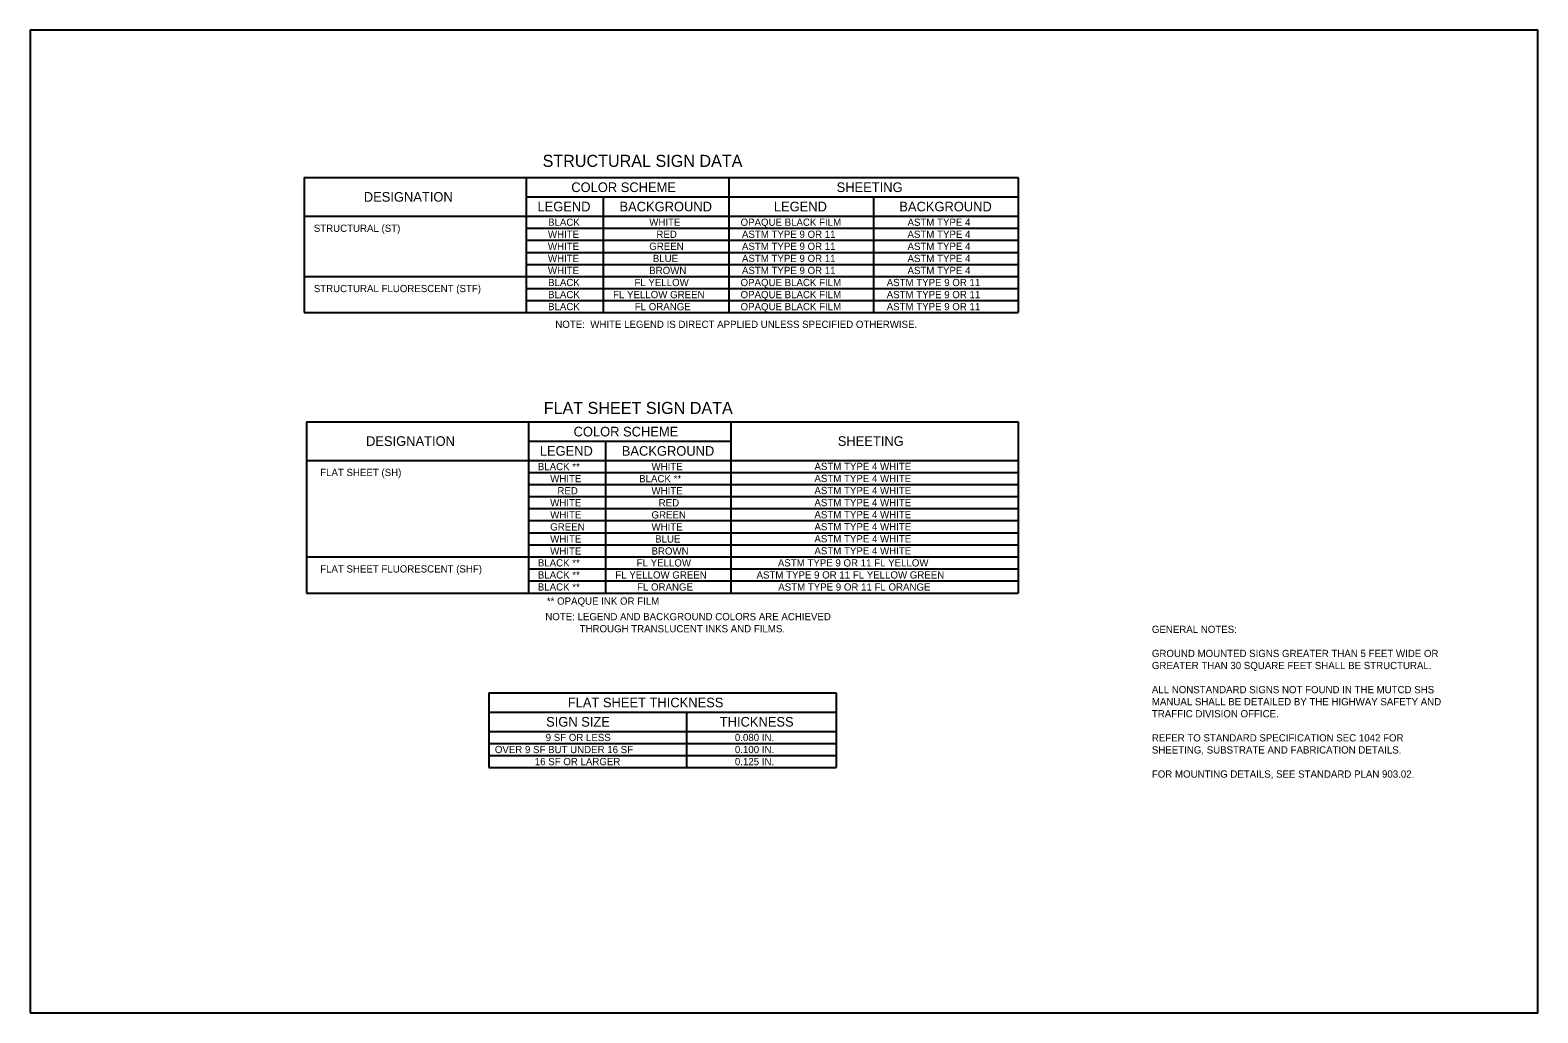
# Model space of a CAD drawing. Extents: x -439.1 to -407.9, y -458.1 to -437.7.
import ezdxf

# ---------------------------------------------------------------- set-up
doc = ezdxf.new("R2010")
doc.units = 0
for name, color, linetype in [('Draft_Named_Boundary', 7, 'Continuous'), ('Level 4', 7, 'Continuous'), ('Level 45', 7, 'Continuous')]:
    doc.layers.add(name, color=color, linetype=linetype)

msp = doc.modelspace()

# ---------------------------------------------------------------- linework, layer by layer
at = {"layer": 'Draft_Named_Boundary'}
msp.add_lwpolyline([(-439.109, -458.051), (-407.859, -458.051), (-407.859, -437.676), (-439.109, -437.676)], close=True, dxfattribs=at)
at = {"layer": 'Level 4'}
for p, q in [((-433.43, -440.733), (-433.43, -443.533)), ((-433.43, -440.733), (-418.63, -440.733)), ((-428.83, -440.733), (-428.83, -443.533)), ((-424.63, -440.733), (-424.63, -443.533)), ((-418.63, -440.733), (-418.63, -443.533)), ((-428.83, -441.133), (-418.63, -441.133)), ((-427.23, -441.133), (-427.23, -443.533)), ((-421.63, -441.133), (-421.63, -443.533)), ((-433.43, -441.533), (-418.63, -441.533)), ((-428.83, -441.783), (-418.63, -441.783)), ((-428.83, -442.033), (-418.63, -442.033)), ((-428.83, -442.283), (-418.63, -442.283)), ((-433.43, -442.783), (-418.63, -442.783)), ((-428.83, -442.533), (-418.63, -442.533)), ((-428.83, -443.033), (-418.63, -443.033)), ((-428.83, -443.283), (-418.63, -443.283)), ((-433.43, -443.533), (-418.63, -443.533)), ((-433.384, -445.796), (-433.384, -449.35)), ((-433.384, -445.796), (-418.629, -445.796)), ((-428.783, -445.8), (-428.783, -449.35)), ((-424.583, -445.8), (-424.583, -449.35)), ((-418.629, -445.796), (-418.629, -449.35)), ((-428.783, -446.196), (-424.583, -446.196)), ((-427.183, -446.2), (-427.183, -449.35)), ((-433.384, -446.596), (-418.629, -446.596)), ((-428.784, -446.846), (-418.629, -446.846)), ((-428.784, -447.096), (-418.629, -447.096)), ((-428.784, -447.346), (-418.629, -447.346)), ((-428.784, -447.596), (-418.629, -447.596)), ((-428.784, -447.846), (-418.629, -447.846)), ((-428.784, -448.096), (-418.629, -448.096)), ((-428.784, -448.346), (-418.629, -448.346)), ((-433.384, -448.596), (-418.629, -448.596)), ((-428.784, -448.846), (-418.629, -448.846)), ((-433.383, -449.35), (-418.628, -449.35)), ((-428.784, -449.096), (-418.629, -449.096)), ((-428.783, -449.096), (-418.629, -449.096)), ((-429.602, -451.416), (-429.602, -452.966)), ((-429.602, -451.416), (-422.402, -451.416)), ((-422.402, -451.416), (-422.402, -452.966)), ((-429.602, -451.816), (-422.402, -451.816)), ((-425.502, -451.816), (-425.502, -452.966)), ((-429.602, -452.216), (-422.402, -452.216)), ((-429.602, -452.466), (-422.402, -452.466)), ((-429.602, -452.716), (-422.402, -452.716)), ((-429.602, -452.966), (-422.402, -452.966))]:
    msp.add_line(p, q, dxfattribs=at)

# ---------------------------------------------------------------- texts
for s, height, p in [('STRUCTURAL SIGN DATA', 0.25, (-428.488, -440.511)), ('COLOR SCHEME', 0.2, (-427.893, -441.033)), ('SHEETING', 0.2, (-422.393, -441.033)), ('DESIGNATION', 0.2, (-432.193, -441.233)), ('LEGEND', 0.2, (-428.594, -441.433)), ('BACKGROUND', 0.2, (-426.894, -441.433)), ('LEGEND', 0.2, (-423.694, -441.433)), ('BACKGROUND', 0.2, (-421.094, -441.433)), ('STRUCTURAL (ST)', 0.15, (-433.23, -441.858)), ('WHITE', 0.15, (-428.377, -441.983)), ('BLACK', 0.15, (-428.374, -441.733)), ('WHITE', 0.15, (-426.277, -441.733)), ('RED', 0.15, (-426.128, -441.983)), ('OPAQUE BLACK FILM', 0.15, (-424.384, -441.733)), ('ASTM TYPE 9 OR 11', 0.15, (-424.355, -441.983)), ('ASTM TYPE 4', 0.15, (-420.924, -441.733)), ('ASTM TYPE 4', 0.15, (-420.924, -441.983)), ('WHITE ', 0.15, (-428.377, -442.233)), ('GREEN', 0.15, (-426.277, -442.233)), ('ASTM TYPE 9 OR 11', 0.15, (-424.355, -442.233)), ('ASTM TYPE 4', 0.15, (-420.924, -442.233)), ('WHITE', 0.15, (-428.377, -442.483)), ('BLUE', 0.15, (-426.202, -442.483)), ('ASTM TYPE 9 OR 11', 0.15, (-424.355, -442.483)), ('ASTM TYPE 4', 0.15, (-420.924, -442.483)), ('WHITE', 0.15, (-428.377, -442.733)), ('BROWN', 0.15, (-426.277, -442.733)), ('ASTM TYPE 9 OR 11', 0.15, (-424.355, -442.733)), ('ASTM TYPE 4', 0.15, (-420.924, -442.733)), ('STRUCTURAL FLUORESCENT (STF)', 0.15, (-433.23, -443.108)), ('BLACK', 0.15, (-428.374, -442.983)), ('BLACK', 0.15, (-428.374, -443.233)), ('FL YELLOW GREEN', 0.15, (-427.027, -443.233)), ('FL YELLOW', 0.15, (-426.584, -442.983)), ('OPAQUE BLACK FILM', 0.15, (-424.384, -442.983)), ('OPAQUE BLACK FILM', 0.15, (-424.384, -443.233)), ('ASTM TYPE 9 OR 11', 0.15, (-421.355, -442.983)), ('ASTM TYPE 9 OR 11', 0.15, (-421.355, -443.233)), ('BLACK', 0.15, (-428.374, -443.483)), ('FL ORANGE', 0.15, (-426.577, -443.483)), ('OPAQUE BLACK FILM', 0.15, (-424.384, -443.483)), ('ASTM TYPE 9 OR 11', 0.15, (-421.355, -443.483)), ('NOTE:  WHITE LEGEND IS DIRECT APPLIED UNLESS SPECIFIED OTHERWISE.', 0.15, (-428.224, -443.85)), ('FLAT SHEET SIGN DATA', 0.25, (-428.465, -445.634)), ('COLOR SCHEME', 0.2, (-427.845, -446.1)), ('DESIGNATION', 0.2, (-432.147, -446.296)), ('SHEETING', 0.2, (-422.369, -446.296)), ('LEGEND', 0.2, (-428.546, -446.5)), ('BACKGROUND', 0.2, (-426.846, -446.5)), ('FLAT SHEET (SH)', 0.15, (-433.098, -446.921)), ('BLACK **', 0.15, (-428.586, -446.8)), ('WHITE', 0.15, (-426.23, -446.8)), ('ASTM TYPE 4 WHITE', 0.15, (-422.853, -446.796)), ('WHITE', 0.15, (-428.33, -447.05)), ('RED', 0.15, (-428.181, -447.3)), ('BLACK **', 0.15, (-426.486, -447.05)), ('WHITE', 0.15, (-426.23, -447.3)), ('ASTM TYPE 4 WHITE', 0.15, (-422.853, -447.046)), ('ASTM TYPE 4 WHITE', 0.15, (-422.853, -447.296)), ('WHITE', 0.15, (-428.33, -447.55)), ('RED', 0.15, (-426.081, -447.55)), ('ASTM TYPE 4 WHITE', 0.15, (-422.853, -447.546)), ('WHITE', 0.15, (-428.33, -447.8)), ('GREEN', 0.15, (-426.23, -447.8)), ('ASTM TYPE 4 WHITE', 0.15, (-422.853, -447.796)), ('GREEN', 0.15, (-428.33, -448.05)), ('WHITE', 0.15, (-426.23, -448.05)), ('ASTM TYPE 4 WHITE', 0.15, (-422.853, -448.046)), ('WHITE', 0.15, (-428.33, -448.3)), ('WHITE', 0.15, (-428.33, -448.55)), ('BROWN', 0.15, (-426.23, -448.55)), ('BLUE', 0.15, (-426.155, -448.3)), ('ASTM TYPE 4 WHITE', 0.15, (-422.853, -448.296)), ('ASTM TYPE 4 WHITE', 0.15, (-422.853, -448.546)), ('BLACK **', 0.15, (-428.586, -448.796)), ('FL YELLOW', 0.15, (-426.537, -448.796)), ('ASTM TYPE 9 OR 11 FL YELLOW', 0.15, (-423.61, -448.796)), ('FLAT SHEET FLUORESCENT (SHF)', 0.15, (-433.098, -448.921)), ('BLACK **', 0.15, (-428.586, -449.046)), ('FL YELLOW GREEN', 0.15, (-426.98, -449.046)), ('ASTM TYPE 9 OR 11 FL YELLOW GREEN', 0.15, (-424.053, -449.046)), ('BLACK **', 0.15, (-428.586, -449.296)), ('FL ORANGE', 0.15, (-426.53, -449.296)), ('ASTM TYPE 9 OR 11 FL ORANGE', 0.15, (-423.603, -449.296)), ('** OPAQUE INK OR FILM', 0.15, (-428.399, -449.588)), ('NOTE: LEGEND AND BACKGROUND COLORS ARE ACHIEVED ', 0.15, (-428.431, -449.911)), ('  THROUGH TRANSLUCENT INKS AND FILMS.', 0.15, (-427.831, -450.161)), ('FLAT SHEET THICKNESS', 0.2, (-427.965, -451.716)), ('SIGN SIZE', 0.2, (-428.415, -452.116)), ('THICKNESS', 0.2, (-424.815, -452.116)), ('9 SF OR LESS', 0.15, (-428.424, -452.416)), ('0.080 IN.', 0.15, (-424.502, -452.416)), ('OVER 9 SF BUT UNDER 16 SF ', 0.15, (-429.477, -452.666)), ('16 SF OR LARGER', 0.15, (-428.649, -452.916)), ('0.100 IN.', 0.15, (-424.502, -452.666)), ('0.125 IN.', 0.15, (-424.502, -452.916))]:
    msp.add_text(s, height=height, dxfattribs=at).set_placement(p)
at = {"layer": 'Level 45'}
for s, p in [('GENERAL NOTES:', (-415.859, -450.174)), ('GROUND MOUNTED SIGNS GREATER THAN 5 FEET WIDE OR ', (-415.859, -450.674)), ('GREATER THAN 30 SQUARE FEET SHALL BE STRUCTURAL.', (-415.859, -450.924)), ('ALL NONSTANDARD SIGNS NOT FOUND IN THE MUTCD SHS', (-415.859, -451.424)), ('MANUAL SHALL BE DETAILED BY THE HIGHWAY SAFETY AND', (-415.859, -451.674)), ('TRAFFIC DIVISION OFFICE.', (-415.859, -451.924)), ('REFER TO STANDARD SPECIFICATION SEC 1042 FOR', (-415.859, -452.424)), ('SHEETING, SUBSTRATE AND FABRICATION DETAILS.', (-415.859, -452.674)), ('FOR MOUNTING DETAILS, SEE STANDARD PLAN 903.02.', (-415.859, -453.174))]:
    msp.add_text(s, height=0.15, dxfattribs=at).set_placement(p)

doc.saveas('drawing.dxf')
